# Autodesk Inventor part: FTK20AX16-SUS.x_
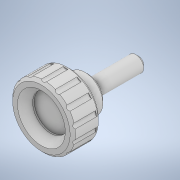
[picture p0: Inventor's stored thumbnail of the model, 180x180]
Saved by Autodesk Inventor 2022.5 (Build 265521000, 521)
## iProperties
Created: 2023-10
Part Number: FTK20AX16-SUS.x_
Material: 一般
Document SubType Name: Modeling
Designer: ImaoCorp
Density: 1 g/cm^3
Appearance: 既定
Sending System: SOLIDWORKS 2021-2021301
MC: AMD64
MC_MODEL: Intel64 Family 6 Model 60 Stepping 3, GenuineIntel
OS: Windows_NT
FRU: Parasolid Version 32.1, build 255,  1- 1-2021
FORMAT: text
GUISE: transmit
KEY: FTK20AX16-SUS
FILE: FTK20AX16-SUS.x_t
DATE: Tue Oct 17 11:07:19 2023
Author: ImaoCorp
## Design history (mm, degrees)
feature "Base1"
node "ソリッド1"
